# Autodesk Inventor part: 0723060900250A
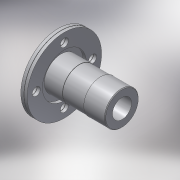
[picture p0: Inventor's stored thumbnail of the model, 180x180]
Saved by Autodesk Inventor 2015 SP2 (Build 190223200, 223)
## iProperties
Created: 2017-02
Part Number: 0723060900250A
Material: PVC-Piping
Description: PLASSON FLANGE ADAPTOR WITH METAL FLANGE 90-2.1/2"
Document SubType Name: Modeling
Designer: KIM
Mass: 92.6774 g
Surface Area: 199.44 cm^2
Volume: 66.1981 cm^3
Density: 1.4 g/cm^3
Appearance: Smooth - White
Author: Кирилл
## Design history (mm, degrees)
derived "872306.ipt"
feature "Solid1::872306.ipt"
tag "TaggingFeature1"
body "Solid1"
other parameters: "d73" = 17.5, "d74" = 90 deg, "d75" = 0.3, "d76" = 185, "d77" = 18, "d78" = 72.5, "d80" = 0, "d82" = 360 deg, "d94" = 65, "d96" = 0.3, "d99" = 360 deg, "d103" = 175, "d104" = 1.8, "d107" = 117, "d108" = 4.375, "d116" = 88.2, "d117" = 58.33333, "d118" = 58.33333, "d120" = 4.5, "H_" = 175, "D_" = 185, "Dp_" = 145, "S_" = 18, "DN_" = 65
